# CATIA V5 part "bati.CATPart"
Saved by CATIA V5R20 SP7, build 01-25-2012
Part number: bati
Publications: "droite_bati_1", "droite_bati_2", "droite_bati_3", "droite_pivot-bati_1", "droite_pivot_bati_3", "droite_pivot_bati_7"
Bounding box of the stored display mesh (mm): x -0.5 to 0, y 0 to 2.4, z -1 to 0
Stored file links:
  U:\IAO\bati.CATPart
  U:\IAO\skl_brevet_iao.CATProduct
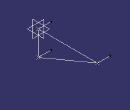
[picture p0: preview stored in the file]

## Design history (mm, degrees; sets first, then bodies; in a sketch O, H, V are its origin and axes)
Set1
  Point1 "point A": linked copy from another document
  Point2 "point H": linked copy from another document
  Point3 "point D": linked copy from another document
Set2
  Line1 "droite_bati_1": type PtPt, FirstPoint Point1, SecondPoint Point2
  Line2 "droite_bati_2": type PtPt, FirstPoint Point2, SecondPoint Point3
  Line3 "droite_bati_3": type PtPt, FirstPoint Point3, SecondPoint Point1
  Line4 "droite_pivot-bati_1": type Normal, RefPoint Point1, RefSkin yz-plane, Start 0, End 0.5
  Line5 "droite_pivot_bati_3": type Normal, RefPoint Point3, RefSkin yz-plane, Start 0, End 0.5
  Line6 "droite_pivot_bati_7": type Normal, RefPoint Point2, RefSkin yz-plane, Start 0, End 0.5
Body1 (main body)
